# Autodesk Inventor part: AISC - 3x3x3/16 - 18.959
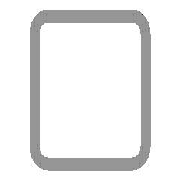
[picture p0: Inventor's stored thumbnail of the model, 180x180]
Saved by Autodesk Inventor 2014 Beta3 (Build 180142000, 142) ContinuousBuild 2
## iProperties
_CCFamilyMember: 9
_CCFamilyDisplayName: ANSI AISC (Square) - Tube
_FrameMemberDoc: Frame Member File
_Version: 15.0.0
_GetPNFromCC: 1
Created: 2011-11
Part Number: AISC - 3x3x3/16 - 18.959
Material: Steel, Mild
Description: Tube
Document SubType Name: Modeling
Standard: ANSI
Designer: Thom Tremblay
Standards Organization: ANSI
Language: en-US
Size Designation: 3x3x3/16
Categories: <MemberInstance><Categories><Category DisplayName="Structural Shapes" InternalName="089c4875-fa83-4c05-b084-43b9cc11f5ed" Mnemonic="GRDR"><CategoryParameter Dis
Stock Number: 3x3x3/16
Density: 7.86 g/cm^3
Appearance: Steel
IsCustomPart: 1
G_L: 18.959 in
G_W: 3.000 in
G_H: 3.000 in
Author: Thom Tremblay
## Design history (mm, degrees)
node "Start plane"
node "End plane"
node "Driven Length"
  sketch "Sketch3"
    geometry: L1 (0, 0)-(10, 0) reference
    constraints: 2 end point, 1 horizontal
  workplane "Work Plane3"
  sketch "Sketch4"
    geometry: L1 (-2, 0)-(12, 0) reference; L2 (-53.34, 481.559)-(53.34, 481.559) reference
    dimensions: "d19" = 481.55872 distance between parallel lines of L1 L2 (derived)
sketch "Sweep Path"
  geometry: L1 through (609.6, 0) direction (1, 0); 1 other entity
  constraints: 5 horizontal
node "Orientation Work Plane"
feature "Body" dims "d20" = 0
body "Solid1"
sketch "Sketch"
  geometry: L1 (-38.1, -28.575)-(-38.1, 28.575); L2 (-28.575, 38.1)-(28.575, 38.1); L3 (38.1, 28.575)-(38.1, -28.575); L4 (28.575, -38.1)-(-28.575, -38.1); L5 (-28.575, 33.337)-(28.575, 33.338); L6 (33.338, 28.575)-(33.338, -28.575); L7 (28.575, -33.337)-(-28.575, -33.338); L8 (-33.338, -28.575)-(-33.338, 28.575); L9 (0, 36.948)-(0, -36.948); L10 (-23.079, 0)-(23.079, 0); A1 r 9.525 centre (-28.575, -28.575) between (-38.1, -28.575) and (-28.575, -38.1); A2 r 9.525 centre (-28.575, 28.575) between (-28.575, 38.1) and (-38.1, 28.575); A3 r 9.525 centre (28.575, 28.575) between (38.1, 28.575) and (28.575, 38.1); A4 r 9.525 centre (28.575, -28.575) between (28.575, -38.1) and (38.1, -28.575); A5 r 4.763 centre (-28.575, 28.575) between (-28.575, 33.337) and (-33.338, 28.575); A6 r 4.763 centre (28.575, 28.575) between (33.338, 28.575) and (28.575, 33.338); A7 r 4.763 centre (28.575, -28.575) between (28.575, -33.337) and (33.338, -28.575); A8 r 4.763 centre (-28.575, -28.575) between (-33.338, -28.575) and (-28.575, -33.338)
  constraints: 20 end point, 16 point on circle, 8 centre point, 8 tangent, 4 parallel, 3 equal radius, 2 perpendicular, 7 other
  dimensions: "d10" = 76.2 distance between parallel lines of L2 L4 (= G_H); "d11" = 76.2 distance between parallel lines of L1 L3 (= G_W); "d12" = 4.7625 distance between parallel lines of L3 L6 (= G_T); "d15" = 38.1 distance between parallel lines of L2 L10 (= 0.5 x d10); "d16" = 38.1 distance between parallel lines of L9 L3 (= 0.5 x d11); "d17" = 9.525 radius of A1 (= G_IR)
other parameters: "G_W" = 76.2 [user parameter; used in 1 equation term], "G_H" = 76.2 [user parameter; used in 1 equation term], "G_T" = 4.7625 [user parameter; used in 1 equation term], "G_IR" = 9.525 [user parameter; used in 1 equation term], "G_L" = 481.55872 (= d19) [user parameter], "G_OFFSET_START" = 0 [user parameter; used in 1 equation term], "G_OFFSET_END" = 0 [user parameter; used in 1 equation term], "d13" = 0 (computed from G_OFFSET_START), "d14" = 481.55872 (= G_OFFSET_END + B_L), "B_L" = 481.55872 [user parameter; used in 1 equation term], "d18" = 90 deg
